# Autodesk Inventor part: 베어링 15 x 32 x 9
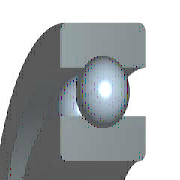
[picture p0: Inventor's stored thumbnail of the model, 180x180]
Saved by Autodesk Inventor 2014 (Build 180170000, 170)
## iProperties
IsCustomPart: 0
Created: 2012-02
Part Number: 베어링 15 x 32 x 9
Material: 강철, 연강
Description: 깊은 그루브 볼 베어링
Document SubType Name: Modeling
Standard: KS B 2023
Designer: mduedu
Standards Organization: KS
Language: ko-KR
Size Designation: 6002 - 15 x 32 x 9
Categories: <MemberInstance><Categories><Category DisplayName="샤프트 부품" InternalName="7f7aeb1f-a693-4053-b835-cee3144e0d98" Mnemonic="SHFT"><Category DisplayName="베어링" Inter
Density: 7.86 g/cm^3
Mass: 27.6801 g
Surface Area: 39.9079 cm^2
Volume: 3.52164 cm^3
Appearance: 노란색
Author: mduedu
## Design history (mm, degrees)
sketch "스케치" dims "d0" = 4.42 (= -0.26 x WD + 0.26 x BD)
  geometry: L1 (2.29, 11.75)-(6.71, 11.75); L2 (4.5, 11.75)-(4.5, 9.54); L3 (4.5, 11.75)-(4.5, 13.96); L4 (2.858, 10.271)-(0, 10.271); L5 (0, 7.5)-(9, 7.5); L6 (2.858, 13.229)-(0, 13.229); L7 (0, 16)-(9, 16); L8 (9, 7.5)-(9, 10.271); L9 (6.142, 10.271)-(9, 10.271); L10 (6.142, 13.229)-(9, 13.229); L11 (9, 16)-(9, 13.229); L12 (-1.4, 0)-(8.4, 0) reference; L13 (0, -0.3)-(0, 5.3) reference
  constraints: 22 end point, 4 point on line, 2 collinear, 2 perpendicular, 2 symmetric about line, 1 midpoint, 1 parallel, 14 other
  dimensions: "d9" = 15 diameter of L5 L12 (= WD); "d11" = 32 diameter of L7 L12 (= BD); "d12" = 9 distance between parallel lines of L8 L13 (= KB); "d13" = 20.542 diameter of L9 L12 (= 0.326 x BD + 0.674 x WD)
revolve "본체" stored, may be unused: angle "d6" = 90 deg
revolve "볼" stored, may be unused: angle "d7" = 90 deg
pattern_circular "IDS_ARRAYBALL[SIMPL:T]" dims angle "d3" = 360 deg
body "Solid1"
fillet "모깎기1" dims "d1" = 0.3 (= KRS)
other parameters: "WD" = 15 [user parameter; used in 5 equation terms], "BD" = 32 [user parameter; used in 5 equation terms], "KB" = 9 [user parameter; used in 1 equation term], "KRS" = 0.3 [user parameter; used in 1 equation term], "d4" = 0, "d5" = 0, "d8" = 0, "d14" = 0, "d15" = 0, "BBA" = 0 [user parameter], "BC0" = 2850000 [user parameter], "BC" = 5590000 [user parameter], "BR" = 16 (= 0.5 x BD) [user parameter], "WR" = 7.5 (= 0.5 x WD) [user parameter]
